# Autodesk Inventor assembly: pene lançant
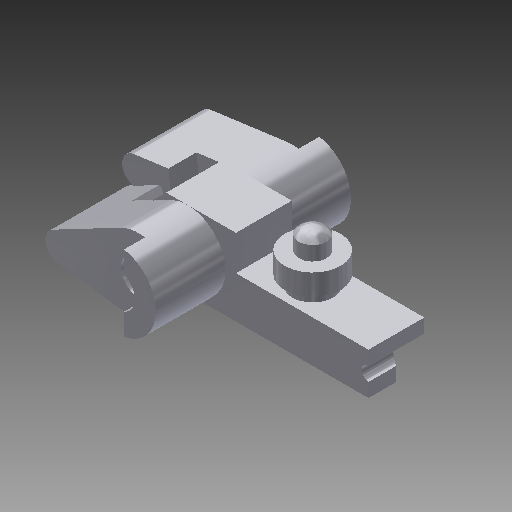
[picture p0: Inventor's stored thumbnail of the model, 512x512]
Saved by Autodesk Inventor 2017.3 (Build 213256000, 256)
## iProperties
Created: 2007-11
Part Number: pene lançant
Material: Générique
Document SubType Name: Assembly
Designer: ficho
Author: ficho
Sending System: SolidWorks 2009
Last Author: christophe
Last Saved: 2011-02-10
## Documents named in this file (6)
- G:\travail\année 2019-2020\réforme\toussaint\Serrure biométrique SET\Documentations_pedagogique\Modelisation_Solidworks\pene lançant.iam
- G:\travail\année 2019-2020\réforme\toussaint\Serrure biométrique SET\Documentations_pedagogique\Modelisation_Solidworks\Pièce5.ipt
- G:\travail\année 2019-2020\réforme\toussaint\Serrure biométrique SET\Documentations_pedagogique\Modelisation_Solidworks\Pièce4.ipt
- G:\travail\année 2019-2020\réforme\toussaint\Serrure biométrique SET\Documentations_pedagogique\Modelisation_Solidworks\axe de noix.ipt
- G:\travail\année 2019-2020\réforme\toussaint\Serrure biométrique SET\Documentations_pedagogique\Modelisation_Solidworks\Pièce6.ipt
- G:\travail\année 2019-2020\réforme\toussaint\Serrure biométrique SET\Documentations_pedagogique\Modelisation_Solidworks\Pièce3.ipt
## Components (6 placed, 5 different names)
1. Pièce5:1
2. Pièce4:1
3. axe de noix:1
4. Pièce6:1
5. Pièce3:3
6. Pièce3:4
